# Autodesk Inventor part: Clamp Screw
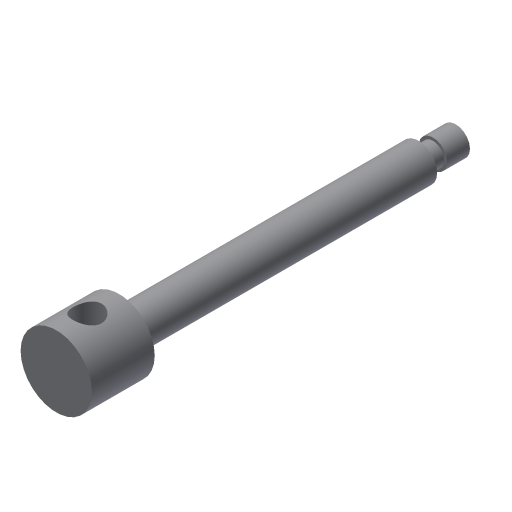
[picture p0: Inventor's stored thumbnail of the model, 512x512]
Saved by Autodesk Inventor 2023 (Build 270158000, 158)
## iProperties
Shininess: 77.0
Length Units: 11269
Angle Units: 11279
Time Units: 11290
Mass Units: 11283
Length Display Precision: 3
Angle Display Precision: 2
Created: 2002-02
Part Number: Clamp Screw
Document SubType Name: Modeling
Designer: ***
Density: 1 g/cm^3
Material: Generic
Appearance: Default
Density: 0.0
Volumn: 0.0
Area: 0.0
PropertySet Name: Model Information
Control State: 0
Master: False
Checked Out: False
Author: ***
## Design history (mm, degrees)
sketch "Sketch1"
  geometry: L1 (0, 140)-(5, 140); L2 (5, 140)-(5, 132); L3 (5, 132)-(4, 132); L4 (4, 132)-(4, 127); L5 (4, 127)-(6.5, 127); L6 (6.5, 127)-(6.5, 25); L7 (6.5, 25)-(4, 25); L8 (4, 25)-(4, 22); L9 (4, 22)-(12.5, 22); L10 (12.5, 22)-(12.5, 0); L11 (12.5, 0)-(0, 0); L12 (0, 0)-(0, 140)
  constraints: 24 end point, 10 parallel, 1 horizontal, 1 perpendicular
  dimensions: "d0" = 10 diameter of L2 L12; "d1" = 8 diameter of L4 L12; "d2" = 13 diameter of L6 L12; "d3" = 8 diameter of L7.end L12; "d4" = 25 diameter of L10 L12; "d5" = 3 distance from line of L7.end L9; "d6" = 8 distance of L1.end L2.end; "d7" = 13 vertical distance of L1.end L5.end; "d8" = 22 distance of L9.end L10.end; "d10" = 102 distance of L5.end L6.end
revolve "Revolution1" sketch "Sketch1" stored, may be unused: angle "d11" = 90 deg
sketch "Sketch3"
  geometry: L1 (-12.5, 0)-(12.5, 0) reference; C1 r 5 at (-0.113, 11)
  constraints: 1 centre point
  dimensions: "d13" = 10 diameter of C1; "d14" = 11 distance from line of L1 C1.centre
extrude "Extrusion1" cut sketch "Sketch3" extent not by distance; stored distance "d15" = 10; taper "d16" = 0 deg
body "Solid1"
